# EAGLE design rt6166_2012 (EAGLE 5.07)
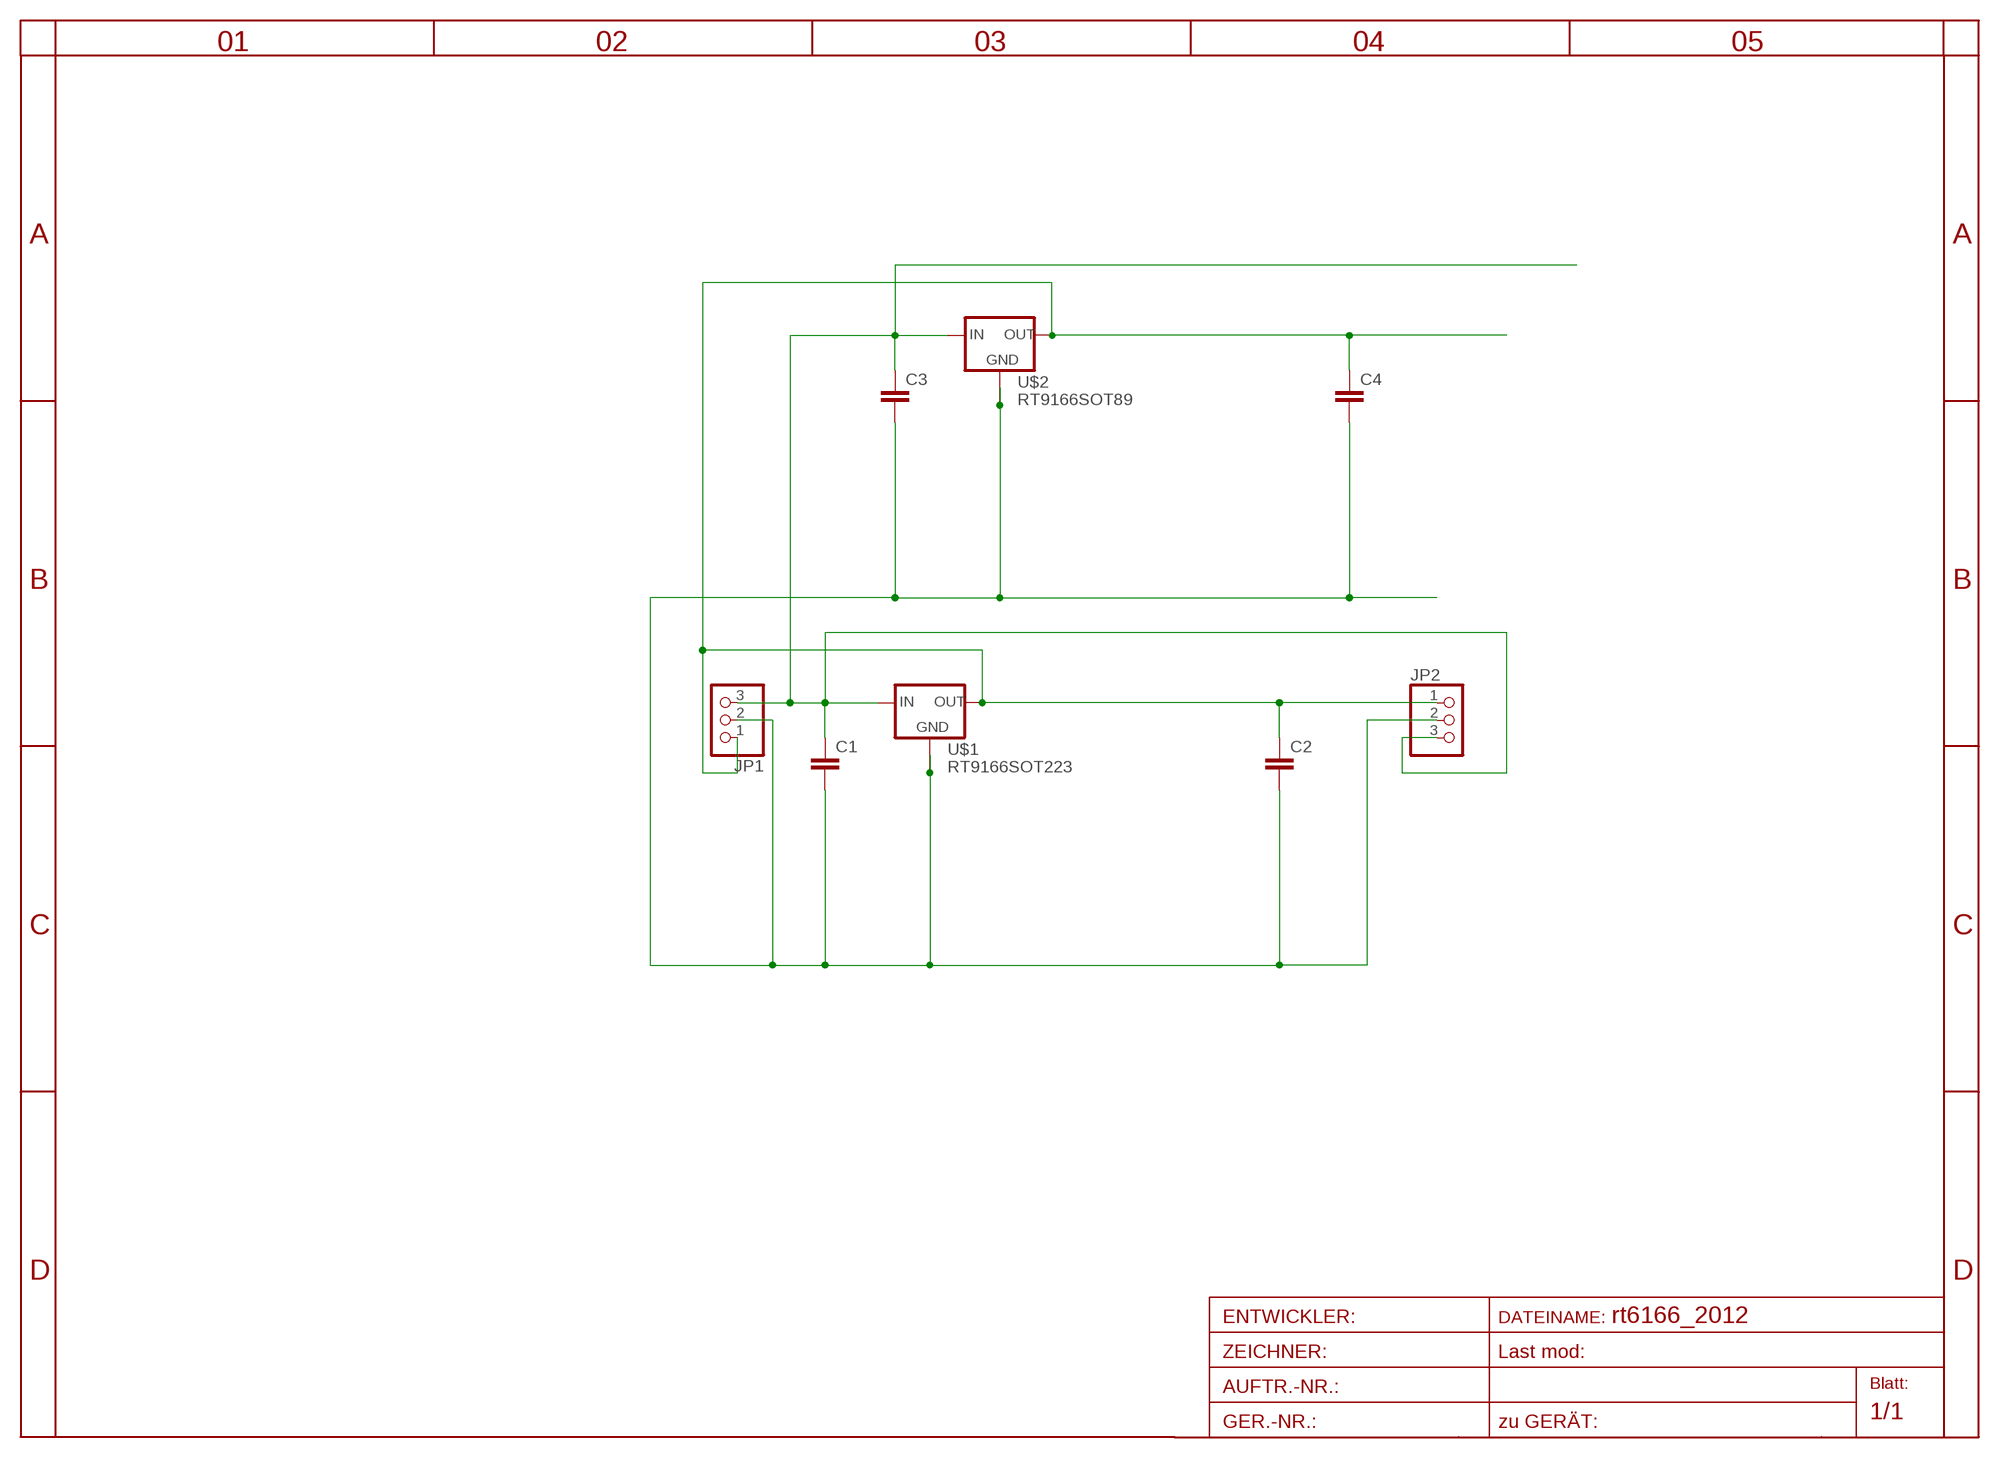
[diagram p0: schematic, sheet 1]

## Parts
C1  C-EUC1206  [C1206]
C2  C-EUC1206  [C1206]
C3  C-EUC1206  [C1206]
C4  C-EUC1206  [C1206]
JP1  PINHD-1X3  [1X03]
JP2  PINHD-1X3  [1X03]
U$1  RT9166SOT223  [SOT223]
U$2  RT9166SOT89  [SOT89R]

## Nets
GND: C1.2 C2.2 C3.2 C4.2 JP1.2 JP2.2 U$1.2(GND) U$1.4(GND1) U$2.3(GND) U$2.4(GND1)
IN: C1.1 C3.1 JP1.3 JP2.3 U$1.3(IN) U$2.1(IN)
OUT: C2.1 C4.1 JP1.1 JP2.1 U$1.1(OUT) U$2.2(OUT)

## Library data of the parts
C1-C4 = rcl:C-EU: CAPACITOR, European symbol
JP1 JP2 = pinhead:PINHD-1X3: PIN HEADER
U$1 U$2 = v-reg:RT9166

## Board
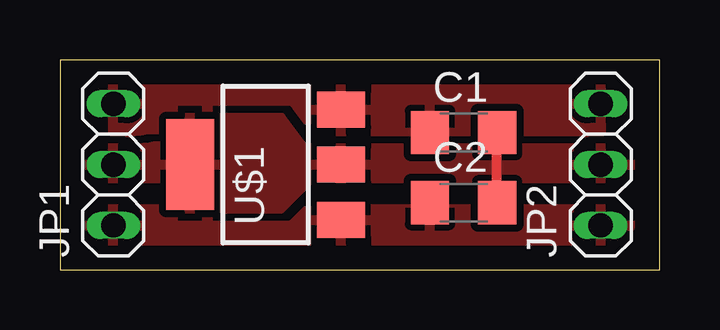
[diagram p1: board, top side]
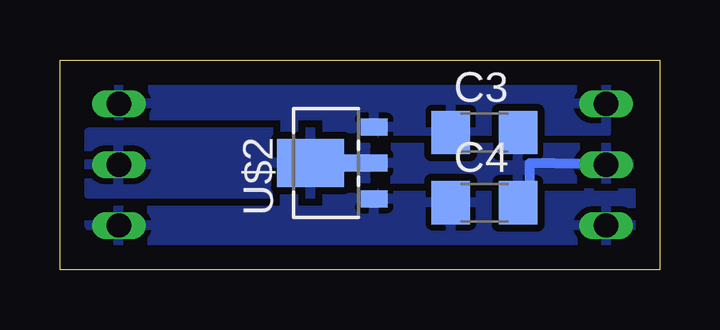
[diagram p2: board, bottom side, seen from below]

Size 25 x 8.75 mm. Coordinates in mm from the lower left corner, seen from the top.
Outline: 0,0 25,0 25,8.75 0,8.75 0,0
Copper layers (1*16): Top 0.035mm / dielectric 1.5mm / Bottom 0.035mm
Design rules "default": minimum track width 10mil, minimum drill 20mil, track to track 8mil, track to pad 8mil, pad to pad 8mil, via to via 8mil, smd to smd 8mil, copper to edge 40mil, drill to drill 8mil, minimum pad ring 1mil, minimum via ring 8mil, stop-mask expansion 4mil, vias tented up to drill 0mil, thermal gap 10mil

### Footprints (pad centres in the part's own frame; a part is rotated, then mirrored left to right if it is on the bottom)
C1206 = smd 1.6 x 1.8: 1 -1.4,0; 2 1.4,0
1X03 = drill 1.016 long: 1 -2.54,0; 2 0,0; 3 2.54,0
SOT223 = smd 1.5 x 2: 1 -2.3,-3.15; 2 0,-3.15; 3 2.3,-3.15 | smd 3.8 x 2: 4 0,3.15
SOT89R = smd 0.7 x 1.1: 1 1.5,-1.75; 2 -1.5,-1.75 | smd 0.7 x 1.8: 3 0,-1.4 | smd 2 x 2.8: 4 0,0.9

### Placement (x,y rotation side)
C1  16.83,5.71 0 top
C2  16.83,2.79 0 top
C3  7.3,5.71 0 bottom
C4  7.3,2.79 0 bottom
JP1  2.22,4.38 90 top
JP2  22.54,4.38 90 top
U$1  8.57,4.38 90 top
U$2  13.65,4.45 90 bottom

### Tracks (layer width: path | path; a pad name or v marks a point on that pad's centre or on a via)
GND
  Top 0.406: C2.2 C1.2
  Bottom 0.406: C4.2 5.42,2.79 5.42,4.45 JP1.2
  pour Top (isolate 0.305): 1.27,5.08 3.49,5.08 arc90 4.76,6.35 9.21,6.35 10.16,5.08 23.81,5.08 23.81,3.81 10.48,3.81 9.21,2.54 5.08,2.54 4.13,3.81 1.27,3.81
  pour Bottom (isolate 0.305): 1.27,5.08 11.43,5.08 12.7,5.71 23.81,5.71 23.81,3.17 13.97,3.17 12.7,3.81 1.27,3.81
IN
  pour Top (isolate 0.305, rank 2): 2.22,5.71 2.22,8.26 22.54,8.26 22.54,5.71
  pour Bottom (isolate 0.305, rank 2): 2.22,5.71 2.22,8.26 22.54,8.26 22.54,5.71
OUT
  pour Top (isolate 0.305, rank 2): 0.95,1.59 0.95,2.22 1.27,2.54 23.5,2.54 23.81,2.22 23.81,1.91 23.18,0.64 1.27,0.64
  pour Bottom (isolate 0.305, rank 2): 0.95,1.59 0.95,3.17 23.18,3.17 23.81,2.22 23.81,1.91 23.18,0.64 1.27,0.64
